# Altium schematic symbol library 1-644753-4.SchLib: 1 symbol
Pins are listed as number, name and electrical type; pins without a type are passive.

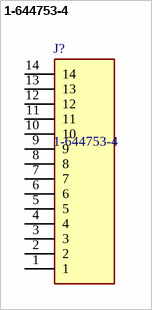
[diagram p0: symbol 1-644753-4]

## 1-644753-4
designator J?
Headers & Wire Housings 14P HDR RN STR F/L; Manufacturer_Name: TE Connectivity; Geometry.Height: 13.589mm
footprint 16447534
pins: 1, 2, 3, 4, 5, 6, 7, 8, 9, 10, 11, 12, 13, 14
